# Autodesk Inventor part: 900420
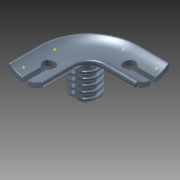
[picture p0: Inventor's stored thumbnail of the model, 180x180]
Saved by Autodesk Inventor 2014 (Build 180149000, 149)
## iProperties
Created: 2007-12
Part Number: 900420
Document SubType Name: Modeling
Designer: DV
Density: 1.13 g/cm^3
Material: Nylon Composite (Nylon, molybdenum disulphide)
Description: WIRE MOUNTING TAB - 90 DEGREE
Mass: 0.710151 g
Surface Area: 11.7735 cm^2
Volume: 0.628452 cm^3
Appearance: Steel Blue
Component Category: Electrical
Author: DV
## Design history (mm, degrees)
sketch "Sketch1"
  geometry: L1 (-3.75, 1.605)-(-3.75, 2.068); L2 (-2.12, 1.835)-(-2.12, 2.144); L3 (-2.782, 2.446)-(-3.75, 1.605); L4 (-3.75, 3.255)-(-3.75, 3.718); L5 (-3.75, 2.068)-(-2.12, 3.485); L6 (-2.782, 4.096)-(-3.75, 3.255); L7 (-2.12, 3.485)-(-2.12, 3.794); L8 (-3.75, 3.718)-(-2.12, 5.135); L9 (-3.75, 4.905)-(-3.75, 5.368); L10 (-2.12, 5.135)-(-2.12, 5.444); L11 (-2.782, 5.746)-(-3.75, 4.905); L12 (-3.75, 5.368)-(-2.12, 6.785); L13 (-3.75, 6.555)-(-3.75, 7.019); L14 (-2.12, 6.785)-(-2.12, 7.094); L15 (-2.782, 7.396)-(-3.75, 6.555); L16 (-3.75, 7.019)-(0, 10.278); L17 (-3.75, 0.418)-(-2.12, 1.835); L18 (-2.12, 0)-(-2.12, 0.494); L19 (-2.9, 0)-(-2.12, 0); L20 (-2.782, 0.796)-(-3.75, -0.045); L21 (-3.75, -0.045)-(-3.75, 0.418); L22 (-2.9, -1.359)-(-2.9, 0); L23 (-4.465, -2.205)-(-4.85, -2.473); L24 (-4.85, -2.473)-(-4.85, -4.314); L25 (-4.111, -3.695)-(-4.85, -4.314); L26 (4.111, -3.695)-(4.85, -4.314); L27 (4.85, -2.473)-(4.85, -4.314); L28 (0, -0.8)-(0, 10.278); L29 (-2.9, -1.359)-(-2.9, -1.881); L30 (-2.9, -1.881)-(0, -1.881); L31 (0, -1.881)-(0, -0.8); A1 r 0.4 centre (-2.52, 2.144) between (-2.12, 2.144) and (-2.782, 2.446); A2 r 6.4 centre (0, -8.6) between (4.111, -3.695) and (-4.111, -3.695); A3 r 0.4 centre (-2.52, 5.444) between (-2.12, 5.444) and (-2.782, 5.746); A4 r 0.4 centre (-2.52, 7.094) between (-2.12, 7.094) and (-2.782, 7.396); A5 r 0.4 centre (-2.52, 3.794) between (-2.12, 3.794) and (-2.782, 4.096); A6 r 0.4 centre (-2.52, 0.494) between (-2.12, 0.494) and (-2.782, 0.796); A7 r 7.8 centre (0, -8.6) between (4.85, -2.491) and (-4.465, -2.205); 2 further points
  constraints: 62 end point, 17 point on circle, 13 parallel, 12 tangent, 8 collinear, 7 centre point, 3 horizontal alignment, 2 vertical, 2 vertical alignment, 1 horizontal, 1 perpendicular, 1 point on line
  dimensions: "d2" = 9.7 distance between parallel lines of L27 L24; "d3" = 1.84109 distance of L23.end L24.end; "d4" = 6.4 radius of A2; "d6" = 4.85 distance from line of L24 point (0, 0); "d7" = 0.8 distance of point (0, 0) L28.start; "d8" = 2.2 distance of point (0, -2.2) point (0, 0); "d9" = 4.31429 vertical distance of L26.end point (0, 0); "d10" = 2.49119 vertical distance of point (0, 0) A7.start; "d11" = 7.8 radius of A7; "d12" = 3.75 distance between parallel lines of L28 L13; "d13" = 2.12 distance between parallel lines of L28 L14; "d14" = 2.52 distance from line of L28 A4.centre; "d15" = 0.4 radius of A4; "d16" = 3.18436 vertical distance of L16.end A4.centre; "d17" = 49 deg angle of L28 L16; "d18" = 0.4 radius of A3 (= d15); "d19" = 0.4 radius of A5 (= d15); "d20" = 0.4 radius of A1 (= d15); "d21" = 0.4 radius of A6 (= d15); "d22" = 0.30908 distance of L12.end L14.end; "d23" = 0.30908 distance of L8.end L10.end (= d22); "d24" = 0.30908 distance of L5.end L7.end (= d22); "d25" = 0.30908 distance of L2.start L2.end (= d22); "d26" = 0.49397 distance of L18.start L18.end; "d27" = 0.4632 distance of L20.end L17.start; "d28" = 0.4632 distance of L1.start L1.end (= d27); "d29" = 0.4632 distance of L4.start L4.end (= d27); "d30" = 0.4632 distance of L9.start L9.end (= d27); "d31" = 2.9 distance from line of L28.start L22; "d71" = 1.88089 distance between parallel lines of L30 L19
revolve "Revolution1" sketch "Sketch1" stored, may be unused: angle "d34" = 90 deg
fillet "Fillet1" dims "d35" = 0.7
workplane "Work Plane1"
sketch "Sketch2"
  geometry: L1 (-1.2, 1.947)-(1.2, 1.947); L2 (-1.2, -1.947)-(1.2, -1.947); L3 (1.2, 3.553)-(1.2, 1.947); L4 (1.2, -1.947)-(1.2, -3.553); L5 (-1.2, -3.553)-(-1.2, -1.947); L6 (-1.2, 1.947)-(-1.2, 3.553); A1 r 3.75 centre (0, 0) between (-1.2, 3.553) and (1.2, 3.553) reference; 3 further points
  constraints: 12 end point, 4 parallel, 4 perpendicular, 4 point on circle, 2 collinear, 2 midpoint, 2 vertical alignment
  dimensions: "d40" = 1.803 distance edge to line of A1 L1; "d41" = 1.803 distance edge to line of A1 L2 (= d40); "d42" = 2.4 distance of L1.start L1.end
extrude "Extrusion2" cut sketch "Sketch2" distance "d43" = 10.8; taper "d44" = 0 deg
workplane "Work Plane2"
sketch "Sketch4"
  geometry: L1 (6.111, -3.695)-(6.85, -4.314); L2 (6.85, -2.473)-(6.85, -4.314); L3 (-2.465, -2.205)-(-2.85, -2.473); L4 (-2.85, -2.473)-(-2.85, -4.314); L5 (-2.111, -3.695)-(-2.85, -4.314); A1 r 6.4 centre (2, -8.6) between (6.111, -3.695) and (-2.111, -3.695); A2 r 7.8 centre (2, -8.6) between (6.85, -2.491) and (-2.465, -2.205); 4 further points
  constraints: 10 end point, 6 point on circle, 3 horizontal alignment, 3 tangent, 2 centre point, 2 vertical alignment, 1 parallel, 1 point on line, 1 vertical
  dimensions: "d52" = 9.7 distance between parallel lines of L2 L4; "d53" = 1.84109 distance of L3.end L4.end; "d54" = 6.4 radius of A1; "d55" = 4.85 distance from line of L4 point (2, 0); "d56" = 0.8 distance of point (2, 0) point (2, -0.8); "d57" = 2.2 distance of point (2, -2.2) point (2, 0); "d58" = 4.31429 vertical distance of L1.end point (2, 0); "d59" = 2.49119 vertical distance of point (2, 0) A2.start; "d60" = 7.8 radius of A2; "d67" = 2 distance of point (0, 0) point (2, 0)
sketch "Sketch5"
  geometry: L1 (2, -15)-(2, -6); L2 (-7, 3)-(-16, 3); A1 r 9 centre (-7, -6) between (2, -6) and (-7, 3); 2 further points
  constraints: 4 end point, 2 point on circle, 2 point on line, 2 tangent, 1 centre point, 1 perpendicular, 1 vertical
  dimensions: "d65" = 18 distance of L1.start point (2, 3); "d66" = 18 distance of point (2, 3) L2.end (= d65); "d68" = 9 radius of A1
sweep "Sweep1" sketch "Sketch4", "Sketch5" dims "d70" = 0
fillet "Fillet5" dims "d72" = 0.45
fillet "Fillet6" dims "d73" = 0.9
fillet "Fillet7" dims "d74" = 0.2
sketch "Sketch3"
  geometry: L1 (-16, -1.351)-(-16, 7.351) reference; L2 (6.351, -15)-(-2.351, -15) reference; L3 (-16, 3.72)-(-10.785, 3.72); L4 (-10.785, 2.28)-(-16, 2.28); L5 (-16, 2.28)-(-16, 3.72); L6 (1.28, -15)-(2.72, -15); L7 (2.72, -15)-(2.72, -9.785); L8 (1.28, -9.785)-(1.28, -15); L9 (-16, 3)-(-9.3, 3); L10 (2, -8.3)-(2, -15); A1 r 1.65 centre (-9.3, 3) between (-10.785, 2.28) and (-10.785, 3.72); A2 r 1.65 centre (2, -8.3) between (2.72, -9.785) and (1.28, -9.785); 3 further points
  constraints: 16 end point, 4 midpoint, 4 point on circle, 3 perpendicular, 2 centre point, 2 coincident, 2 horizontal, 2 parallel, 2 point on line, 1 horizontal alignment, 1 vertical, 1 vertical alignment
  dimensions: "d78" = 1.65 radius of A1; "d79" = 1.65 radius of A2 (= d78); "d80" = 1.44 distance between parallel lines of L3 L4; "d81" = 1.44 distance between parallel lines of L7 L8 (= d80); "d82" = 6.7 distance from line of L5 L9.end; "d83" = 6.7 distance from line of L6 L10.start
extrude "Extrusion4" cut sketch "Sketch3" stored distance "d84" = 10; taper "d85" = 0 deg
workpoint "Work Point4"
workpoint "Work Point5"
workpoint "Work Point6"
workpoint "Work Point7"
body "Solid1"
other parameters: "d39" = 10.75, "d69" = -15, "d86" = 0
